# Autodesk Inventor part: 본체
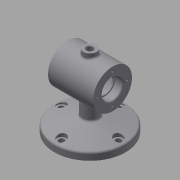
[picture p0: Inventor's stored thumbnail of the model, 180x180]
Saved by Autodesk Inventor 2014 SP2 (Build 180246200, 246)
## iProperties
Created: 2018-12
Part Number: 본체
Material: Generic
Document SubType Name: Modeling
Designer: 거성
Density: 1 g/cm^3
Appearance: Default
Author: 거성
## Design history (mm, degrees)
sketch "스케치1"
  geometry: L1 (-35, 30)-(35, 30); L2 (35, 30)-(35, 0); L3 (35, 0)-(-35, 0); L4 (-35, 0)-(-35, 30); 2 further points
  constraints: 8 end point, 2 parallel, 1 coincident, 1 horizontal, 1 midpoint, 1 perpendicular
  dimensions: "d0" = 70 distance of L2.end L3.end; "d1" = 30 distance of L3.end L1.start
revolve "회전1" sketch "스케치1" stored, may be unused: angle "d2" = 90 deg
sketch "스케치2"
  geometry: L1 (-35, 30)-(-35, -30) reference; L2 (35, 30)-(35, -30) reference; L3 (-35, 0)-(35, 0); L4 (0, 0)-(0, 26.689); L5 (-35, 0)-(-35, 16); L6 (-35, 30)-(-35, -30) reference; L7 (-23, 15.7)-(-23, 14); L8 (-35, 16)-(-23.3, 16); L9 (-23, 14)-(-20, 14); L10 (-20, 14)-(-20, 22); L11 (-17, 25)-(0, 25); L12 (23, 15.7)-(23, 14); L13 (35, 16)-(23.3, 16); L14 (23, 14)-(20, 14); L15 (20, 14)-(20, 22); L16 (35, 30)-(35, -30); L17 (17, 25)-(0, 25); L18 (35, 16)-(35, 0); A1 r 3 centre (-17, 22) between (-17, 25) and (-20, 22); A2 r 3 centre (17, 22) between (20, 22) and (17, 25); A3 r 0.3 centre (-23.3, 15.7) between (-23, 15.7) and (-23.3, 16); A4 r 0.3 centre (23.3, 15.7) between (23.3, 16) and (23, 15.7); 4 further points
  constraints: 30 end point, 10 point on line, 8 point on circle, 8 tangent, 5 symmetric about line, 4 centre point, 3 parallel, 3 perpendicular, 2 midpoint, 1 collinear, 1 equal radius
  dimensions: "d3" = 32 diameter of L8 L3; "d4" = 28 diameter of L9 L3; "d5" = 50 diameter of L11 L3; "d6" = 12 distance of L5.end point (-23, 16); "d7" = 20 distance of point (-20, 25) L11.end; "d54" = 3 radius of A1; "d55" = 0.3 radius of A3; "d56" = 0.3 radius of A4
revolve "회전2" sketch "스케치2" stored, may be unused: angle "d8" = 90 deg
node "작업 평면2"
sketch "스케치3"
  geometry: C1 r 55 at (0, 0); 1 further point
  constraints: 1 centre point, 1 coincident
  dimensions: "d11" = 110 diameter of C1
extrude "돌출1" join sketch "스케치3" distance "d12" = 11; taper "d13" = 0 deg
sketch "스케치4"
  geometry: L1 (55, -64)-(-55, -64) reference; L2 (0, -64)-(0, -49.263); L3 (-55, -64)-(0, -49.263); 1 further point
  constraints: 4 end point, 1 midpoint, 1 perpendicular
  dimensions: "d14" = 15 deg angle of L1 L3
revolve "회전3" sketch "스케치4" stored, may be unused: angle "d15" = 90 deg
node "작업 평면3"
sketch "스케치5"
  geometry: C1 r 12 at (0, 0); 1 further point
  constraints: 1 centre point, 1 coincident
  dimensions: "d17" = 24 diameter of C1
extrude "돌출2" join sketch "스케치5" stored distance "d18" = 10; taper "d19" = 0 deg
sketch "스케치6"
  geometry: A1 r 12 centre (0, 0) between (12, 0) and (-12, 0) reference; A2 r 12 centre (0, 0) between (-12, 0) and (12, 0) reference
extrude "돌출3" join sketch "스케치6" stored distance "d20" = 10; taper "d21" = 0 deg
node "작업 평면4"
sketch "스케치7"
  geometry: C1 r 10 at (0, 0); 1 further point
  constraints: 1 centre point, 1 coincident
  dimensions: "d23" = 20 diameter of C1
extrude "돌출4" join sketch "스케치7" stored distance "d24" = 10; taper "d25" = 0 deg
sketch "스케치8"
  geometry: C1 r 10 at (0, 0) reference; C2 r 5 at (0, 0)
  constraints: 1 centre point, 1 coincident
  dimensions: "d26" = 10 diameter of C2
extrude "돌출5" cut sketch "스케치8" stored distance "d27" = 10; taper "d28" = 0 deg
sketch "스케치9"
  geometry: C1 r 16 at (0, 0) reference; 1 further point
  constraints: 1 vertical alignment
  dimensions: "d29" = 23 distance of C1.centre point (0, 23)
hole "구멍1" sketch "스케치9" at (0, 23) diameter "d30" = 3.242; stored, may be unused: countersink angle "d34" = 90 deg, drill point angle "d36" = 118 deg; dims "d31" = 8, "d32" = 4, "d33" = 2, "d35" = 10
sketch "스케치10"
  geometry: C1 r 55 at (0, 0) reference; 1 further point
  constraints: 1 vertical alignment
  dimensions: "d40" = 44 distance of C1.centre point (0, 44)
hole "구멍2" sketch "스케치10" at (0, 44) diameter "d41" = 9; stored, may be unused: countersink angle "d45" = 90 deg, drill point angle "d47" = 0 deg; dims "d42" = 8, "d43" = 4, "d44" = 2, "d46" = 10
sketch "스케치11"
  geometry: C1 r 4.5 at (0, 0) reference; C2 r 7 at (0, 0); 1 further point
  constraints: 1 centre point, 1 coincident
  dimensions: "d48" = 14 diameter of C2
extrude "돌출6" cut sketch "스케치11" distance "d49" = 20; taper "d50" = 0 deg
fillet "모깎기1" dims "d57" = 3
chamfer "모따기1" distance "d58" = 1; stored, may be unused: second distance "d59" = 2, angle "d60" = 45 deg
node "작업 평면5"
sketch "스케치12"
  geometry: L1 (-24.778, 12.294)-(24.778, 12.294); L2 (24.778, 12.294)-(24.778, -12.294); L3 (24.778, -12.294)-(-24.778, -12.294); L4 (-24.778, -12.294)-(-24.778, 12.294); L5 (-24.778, 12.294)-(24.778, -12.294); L6 (35, 30)-(-35, 30) reference; L7 (-35, 30)-(-35, -30) reference; L8 (24.778, 12.294)-(-24.778, -12.294); 5 further points
  constraints: 4 end point, 4 midpoint, 1 horizontal alignment, 1 vertical alignment, 2 other
extrude "돌출7" join sketch "스케치12" stored distance "d62" = 0.5; taper "d63" = 0 deg
node "솔리드1"
pattern_circular "원형 패턴1" dims angle "d38" = 360 deg
mirror "대칭1"
pattern_circular "원형 패턴2" dims angle "d52" = 360 deg
node "투영된 루프1"
other parameters: "d10" = -75, "d22" = 37, "d61" = 30.5
